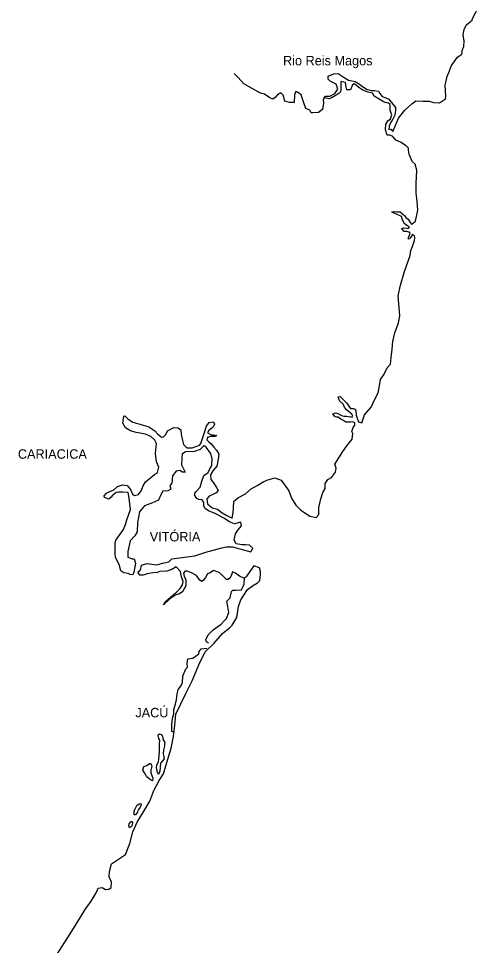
# Model space of a CAD drawing. Extents: x 662444 to 1640468, y 7452018 to 9606170.
# Drawn here: x 978078 to 1009377, y 7720224 to 7783209 of the extents above; entities that cross this region are included whole.
import ezdxf

# ---------------------------------------------------------------- set-up
doc = ezdxf.new("R2010")
doc.units = 0
doc.layers.add('Level 1', color=7, linetype='Continuous')
doc.layers.add('Level 3', color=7, linetype='Continuous')

msp = doc.modelspace()

# ---------------------------------------------------------------- linework, layer by layer
at = {"layer": 'Level 1'}
for points in [[(1003348, 7775684), (1003491, 7775536), (1003648, 7775897), (1003874, 7776435), (1004309, 7776978), (1004794, 7777408), (1005052, 7777612), (1005523, 7777598), (1005786, 7777590), (1005964, 7777585), (1006255, 7777499), (1006654, 7777487), (1007081, 7777753), (1007087, 7777941), (1007056, 7778686), (1007178, 7779260), (1007336, 7779645), (1007483, 7780018), (1007658, 7780257), (1007877, 7780584), (1008038, 7780690), (1008188, 7780786), (1008201, 7780897), (1008195, 7781030), (1008318, 7781304), (1008329, 7781670), (1008268, 7782094), (1008331, 7782470), (1008465, 7782755), (1008659, 7782916), (1008885, 7783109), (1008909, 7783208), (1009377, 7784117)], [(998834, 7777824), (998757, 7777715), (998781, 7777459), (998727, 7777027), (998438, 7776824), (998069, 7776791), (997944, 7776794), (997865, 7776974), (997585, 7777093), (997459, 7777474), (997276, 7778024), (997018, 7778197), (996904, 7778245), (996824, 7778014), (996789, 7777515), (996484, 7777502), (996151, 7777589), (996057, 7777992), (995884, 7778163), (995660, 7778036), (995497, 7777841), (995336, 7777734), (995139, 7777818), (994779, 7778072), (994498, 7778147), (993372, 7778778), (992995, 7779200), (992727, 7779469)], [(1003481, 7775214), (1003294, 7775275), (1003116, 7775280), (1002990, 7775639), (1003012, 7776038), (1003165, 7776256), (1003327, 7776395), (1003418, 7776670), (1003322, 7776962), (1003312, 7777362), (1003200, 7777465), (1002980, 7777494), (1002784, 7777599), (1002237, 7777937), (1002117, 7778140), (1001815, 7778216), (1001462, 7778348), (1001256, 7778487), (1000865, 7778765), (1000758, 7778701), (1000613, 7778372), (1000371, 7778357), (1000334, 7778547), (1000280, 7778871), (999957, 7778924), (999968, 7778591), (999972, 7778346), (999915, 7778193), (999636, 7778001), (999370, 7777853), (999199, 7777747), (998959, 7777809), (998834, 7777824), (998921, 7777943), (999225, 7777935), (999556, 7778125), (999763, 7778408), (999637, 7778756), (999233, 7778945), (999111, 7779082), (999096, 7779282), (999489, 7779448), (999784, 7779484), (1000195, 7779195), (1000474, 7779032), (1000703, 7778970), (1000933, 7778930), (1001222, 7778755), (1001417, 7778605), (1001695, 7778419), (1002028, 7778310), (1002238, 7778326), (1002510, 7778285), (1002620, 7778115), (1002762, 7777922), (1003011, 7777815), (1003218, 7777731), (1003674, 7777163), (1003669, 7776985), (1003664, 7776797), (1003605, 7776598), (1003504, 7776368), (1003351, 7776161), (1003238, 7775887), (1003232, 7775676), (1003348, 7775684)], [(1004567, 7774259), (1004549, 7774394), (1004407, 7774554), (1004005, 7774810), (1003705, 7774952), (1003481, 7775214)], [(1004799, 7769256), (1005035, 7769438), (1005182, 7770178), (1005137, 7770790), (1005090, 7771336), (1005089, 7772024), (1005101, 7772435), (1005125, 7772912), (1005001, 7773315), (1004817, 7773498), (1004601, 7773993), (1004567, 7774259)], [(1004830, 7768522), (1004810, 7768556), (1004775, 7768435), (1004699, 7768326), (1004644, 7768239), (1004549, 7768220), (1004562, 7768330), (1004630, 7768495), (1004665, 7768616), (1004636, 7768695), (1004573, 7768696), (1004448, 7768733), (1004259, 7768739), (1004108, 7768943), (1004235, 7768995), (1004455, 7768955), (1004538, 7768953), (1004625, 7769061), (1004491, 7769132), (1004316, 7769226), (1004156, 7769530), (1004079, 7769766), (1003707, 7769932), (1003437, 7770051), (1003543, 7770092), (1003784, 7770085), (1003984, 7770080), (1004311, 7769792), (1004371, 7769680), (1004546, 7769575), (1004665, 7769349), (1004787, 7769212), (1004799, 7769256)], [(1001158, 7755813), (1001386, 7755729), (1001580, 7756278), (1002025, 7756798), (1002239, 7757303), (1002504, 7757773), (1002581, 7758259), (1002667, 7758679), (1002898, 7759050), (1003109, 7759466), (1003347, 7759725), (1003382, 7760180), (1003440, 7760744), (1003487, 7761265), (1003640, 7761860), (1003870, 7762542), (1003967, 7763017), (1003932, 7763584), (1003850, 7764375), (1004017, 7765092), (1004262, 7765951), (1004433, 7766402), (1004674, 7767116), (1004725, 7767437), (1004838, 7767723), (1004955, 7768119), (1004992, 7768318), (1004975, 7768452), (1004892, 7768498), (1004830, 7768522)], [(1000770, 7755813), (1000622, 7755773), (1000308, 7755793), (1000092, 7755922), (999958, 7755992), (999783, 7756119), (999679, 7756122), (999585, 7756136), (999423, 7756341), (999529, 7756393), (999634, 7756412), (999811, 7756341), (1000007, 7756235), (1000163, 7756186), (1000341, 7756181), (1000466, 7756177), (1000633, 7756150), (1000748, 7756147), (1000781, 7756179), (1000711, 7756315), (1000343, 7756625), (1000222, 7756795), (1000123, 7756998), (999898, 7757204), (999849, 7757306), (999781, 7757507), (999918, 7757526), (1000112, 7757320), (1000305, 7757137), (1000377, 7757068), (1000497, 7756876), (1000618, 7756717), (1000806, 7756700), (1000931, 7756664), (1000991, 7756551), (1001014, 7756250), (1001041, 7756127), (1001158, 7755813)], [(985845, 7745413), (985657, 7745441), (985512, 7745501), (985231, 7745553), (985025, 7745670), (984911, 7746106), (984663, 7746579), (984639, 7746858), (984648, 7747535), (984675, 7747767), (984970, 7748181), (985209, 7748485), (985334, 7748837), (985437, 7749156), (985677, 7749859), (985583, 7750617), (985521, 7751007), (985155, 7751018), (984872, 7751026), (984714, 7751008), (984596, 7750911), (984435, 7750772), (984370, 7750685), (984209, 7750545), (983919, 7750653), (983901, 7750787), (984042, 7750949), (984234, 7751055), (984541, 7751179), (984788, 7751406), (985127, 7751518), (985450, 7751476), (985573, 7751350), (985704, 7751169), (985822, 7750899), (985945, 7750796), (986219, 7750866), (986393, 7751105), (986529, 7751445), (986694, 7751718), (987305, 7752223), (987508, 7752362), (987613, 7752725), (987435, 7753096), (987388, 7753664), (987449, 7754340), (987329, 7754565), (987064, 7754806), (986691, 7754972), (986065, 7755078), (985681, 7755200), (985351, 7755387), (985150, 7755715), (985237, 7756201), (985290, 7756221), (985525, 7755982), (985844, 7755773), (986322, 7755648), (986914, 7755454), (987326, 7755198), (987509, 7754993), (987796, 7754774), (987912, 7754782), (988073, 7754933), (988185, 7755185), (988632, 7755417), (988914, 7755397), (989099, 7755259), (989122, 7754947), (989204, 7754534), (989270, 7754266), (989505, 7754037), (989871, 7754038), (990359, 7754224), (990446, 7754333), (990697, 7755069), (990846, 7755509), (991020, 7755749), (991326, 7755807), (991395, 7755649), (991306, 7755485), (991199, 7755377), (990995, 7755227), (990917, 7755052), (991154, 7754923), (991322, 7754929), (991551, 7754879), (991413, 7754805), (991109, 7754813), (990918, 7754730), (990872, 7754576), (990994, 7754439), (991127, 7754335), (991329, 7754085), (991522, 7753869), (991682, 7753598), (991631, 7753266), (991534, 7752791), (991263, 7752477), (991118, 7752193)], [(991118, 7752193), (991131, 7751892), (991323, 7751654), (991513, 7751337), (991644, 7751134), (991503, 7750971), (991184, 7750814), (991014, 7750752), (990873, 7750578), (990906, 7750244), (991223, 7749969), (991587, 7749881), (991915, 7749616), (992172, 7749453), (992585, 7749252), (992659, 7749650), (992678, 7749949), (992702, 7750404), (993014, 7750673), (993492, 7750903), (993879, 7751248), (994337, 7751501), (994742, 7751745), (994753, 7751756), (994944, 7751839), (995472, 7751990), (995908, 7751845), (996442, 7751107), (996616, 7750614), (996917, 7750150), (997223, 7749830), (997849, 7749401), (998286, 7749300), (998460, 7749505), (998463, 7749983), (998606, 7750567), (998744, 7750996), (998889, 7751281), (998899, 7751625), (999084, 7751886), (999340, 7752023), (999602, 7752393), (999652, 7752658), (999555, 7752939), (1000103, 7753778), (1000377, 7754181), (1000736, 7754637), (1000768, 7755002), (1000719, 7755137), (1000811, 7755412), (1000910, 7755576), (1000925, 7755731), (1000770, 7755813)], [(990111, 7751044), (990403, 7751358), (990530, 7751765), (990667, 7752150), (990955, 7752353), (991067, 7752605), (991210, 7752845), (991224, 7753311), (991108, 7753681), (990816, 7754089), (990693, 7754181), (990608, 7754139), (990413, 7753934), (990022, 7753800), (989423, 7753762), (989199, 7753602), (989160, 7753325), (989147, 7752881), (989325, 7752521), (989395, 7752386), (989196, 7752392), (989052, 7752496), (988789, 7752459), (988539, 7752133), (988483, 7751646), (988342, 7751472), (988408, 7751226), (988206, 7751109), (987881, 7751085), (987748, 7750845), (987591, 7750472), (987177, 7750295), (986637, 7750099), (986291, 7749698), (986155, 7748958), (986126, 7748326), (985982, 7748052), (985659, 7747717), (985502, 7746989), (985502, 7746611), (985782, 7746503), (985939, 7746499), (986014, 7746197), (985965, 7745954), (985913, 7745600), (985845, 7745413)], [(987494, 7745567), (987200, 7745553), (986821, 7745486), (986546, 7745394), (986316, 7745389), (986175, 7745582), (986357, 7745754), (986429, 7746063), (986820, 7746174), (987456, 7746090), (987963, 7746231), (988279, 7746299), (988484, 7746505), (990051, 7746704), (990791, 7746950), (991889, 7747240), (992195, 7747320), (992603, 7747309), (993861, 7746973), (993994, 7747213), (993759, 7747431), (993497, 7747450), (993257, 7747457), (992850, 7747524), (992721, 7747772), (992806, 7748191), (992960, 7748453), (993210, 7748746), (993175, 7748980), (992732, 7748882), (992400, 7749013), (992009, 7749269), (991473, 7749562), (990986, 7749765), (990750, 7749927), (990660, 7750074), (990667, 7750318), (990536, 7750510), (990327, 7750527), (990193, 7750598), (990032, 7750835), (990045, 7750935), (990111, 7751044)], [(980710, 7719622), (981542, 7720942), (982045, 7721738), (982595, 7722677), (983019, 7723231), (983338, 7723789), (983483, 7724106), (983767, 7724154), (983993, 7724036), (984203, 7724053), (984363, 7724170), (984384, 7724536), (984227, 7724885), (984248, 7725251), (984388, 7725780), (985337, 7726408), (985641, 7727143), (985841, 7727937), (986132, 7728606), (986570, 7729293), (986989, 7730025), (987261, 7730761), (987636, 7731428), (987911, 7731897), (988083, 7732436), (988452, 7733625), (988601, 7734431), (988686, 7735195), (988759, 7735948), (989428, 7737350), (989871, 7738215), (990310, 7739290), (990754, 7740177), (991358, 7740771), (991921, 7741432), (992414, 7741817), (992587, 7741990), (992905, 7742503), (993021, 7743255), (993170, 7743706), (993630, 7744403), (993973, 7744671), (994293, 7744862), (994465, 7745034), (994508, 7745422), (994504, 7745644), (994437, 7745879), (994064, 7746023), (993825, 7745708), (993540, 7745272), (993370, 7745188), (993091, 7745318), (992803, 7745515), (992607, 7745610), (992548, 7745400), (992459, 7745214), (992320, 7745096), (992204, 7745099), (991918, 7745352), (991694, 7745558), (991321, 7745713), (991086, 7745542), (990916, 7745469), (990762, 7745218), (990610, 7745023), (990503, 7744948), (990371, 7745074), (990159, 7745369), (989818, 7745534), (989528, 7745653), (989392, 7745657), (989284, 7745516), (989319, 7745304), (989439, 7745089), (989427, 7744657), (989206, 7744263), (988960, 7744093), (988781, 7744053), (988568, 7743937), (988332, 7743744), (987914, 7743378), (988024, 7743575), (988378, 7743865), (988785, 7744197), (989045, 7744490), (989220, 7744740), (989257, 7744950), (989111, 7745343), (989078, 7745644), (988773, 7745963), (988495, 7745782), (988146, 7745648), (987664, 7745640), (987494, 7745567)], [(990981, 7740770), (990847, 7740852), (990799, 7740987), (990944, 7741327), (991300, 7741661), (991610, 7741896), (991845, 7742067), (992030, 7742284), (992191, 7742446), (992349, 7742841), (992299, 7743264), (992225, 7743611), (992354, 7743751), (992451, 7743849), (992548, 7744279), (992623, 7744365), (992843, 7744359), (993221, 7744393), (993410, 7744765), (993422, 7745187)], [(988650, 7734696), (988485, 7734757), (988488, 7735245), (988541, 7735643), (988623, 7735952), (988632, 7736240), (988691, 7736483), (988808, 7736913), (988851, 7737322), (988922, 7737598), (989118, 7737881), (989218, 7738089), (989242, 7738533), (989433, 7739016), (989541, 7739135), (989518, 7739402), (989579, 7739700), (989905, 7739757), (990075, 7739863), (990311, 7740034), (990347, 7740200), (990488, 7740385), (990866, 7740418)], [(988003, 7734004), (987989, 7733894), (987985, 7733760), (987915, 7733485), (987897, 7733252), (987934, 7733062), (987961, 7732906), (987842, 7732765), (987722, 7732613), (987703, 7732314), (987665, 7732071), (987575, 7731851), (987516, 7731986), (987452, 7732310), (987478, 7732487), (987588, 7732695), (987615, 7732883), (987632, 7733138), (987641, 7733437), (987647, 7733659), (987654, 7733892), (987662, 7734181), (987603, 7734293), (987555, 7734472), (987557, 7734539), (987654, 7734614), (987798, 7734543), (987877, 7734363), (987884, 7734252), (988003, 7734004)], [(986765, 7731708), (986665, 7731877), (986515, 7732137), (986585, 7732390), (986786, 7732451), (986978, 7732579), (987062, 7732588), (987120, 7732408), (987060, 7732144), (987065, 7731944), (987133, 7731764), (987201, 7731595), (987165, 7731419), (987031, 7731489), (986928, 7731570), (986765, 7731708)], [(986185, 7729370), (986152, 7729282), (986011, 7729109), (985937, 7729100), (985923, 7729344), (985968, 7729454), (986112, 7729728), (986272, 7729845), (986377, 7729864), (986407, 7729786), (986339, 7729610), (986230, 7729458), (986185, 7729370)], [(985802, 7728404), (985757, 7728305), (985619, 7728221), (985571, 7728377), (985596, 7728499), (985715, 7728651), (985767, 7728649), (985817, 7728570), (985802, 7728404)]]:
    msp.add_lwpolyline(points, dxfattribs=at)

# ---------------------------------------------------------------- texts
at = {"layer": 'Level 3'}
for s, height, p in [('Rio Reis Magos', 644.02, (996037, 7780030)), ('CARIACICA', 642.9, (978034, 7753297)), ('VITÓRIA', 642.7, (986988, 7747680)), ('JACÚ', 642.3, (986012, 7735724))]:
    msp.add_text(s, height=height, dxfattribs=at).set_placement(p)

doc.saveas('drawing.dxf')
